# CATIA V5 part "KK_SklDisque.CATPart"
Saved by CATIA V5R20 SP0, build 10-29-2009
Part number: skl disque
Bounding box of the stored display mesh (mm): x 0 to 0, y 0 to 0, z -20 to 20
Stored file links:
  G:\Khaled_CFAO_2011\ST2M\ST2M_GR2\tcorbin\Khaled\CAD_ThinkMOTION\KK_SklDisque.CATPart
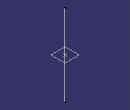
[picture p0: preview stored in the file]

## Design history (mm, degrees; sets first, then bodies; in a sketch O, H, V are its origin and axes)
Set1
  Plane1 "plan_extr_disque": type Offset, RefPlane xy-plane, Offset 0
  Point1 "point_origine_disque": type OnPlane, Support Plane1, H 0, V 0, Direction (1, 0, 0)
  Line1 "axe_perçage": type PtDir, RefPoint Point1, Direction Plane1, Start -20, End 20
Body1 (main body)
